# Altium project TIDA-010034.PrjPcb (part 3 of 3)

## Sheet TIDA-010034 MSP430.SchDoc: MSP430 for accessing registers of DP83825
size 431 x 279 mm; Date: Not shown in title block; ApprovedBy: Not shown in title block; CheckedBy: Not shown in title block; Author: Not shown in title block; CompanyName: Not shown in title block; DrawnBy: Surya Mishra; Engineer: Surya Mishra; Organization: Not shown in title block; Address1: Not shown in title block; Address2: Not shown in title block; Address3: Not shown in title block; Address4: Not shown in title block; DocumentNumber: 1; Revision: E1; SheetNumber: 8; SheetTotal: 9; PageSetup: Record=PageOptions¦CenterHorizontal=True¦CenterVertical=True¦PrintScale=1.00¦XCorrection=1.00¦YCorrection=1.00¦PrintKind=0¦BorderSize=5000000¦LeftOffset=0¦BottomOffset=0¦Orientation=2¦PaperLength=1000¦PaperWidth=1000¦Scale=100¦PaperSource=15¦PrintQuality=600¦MediaType=1¦DitherType=10¦PaperKind=Letter¦PrintScaleMode=1
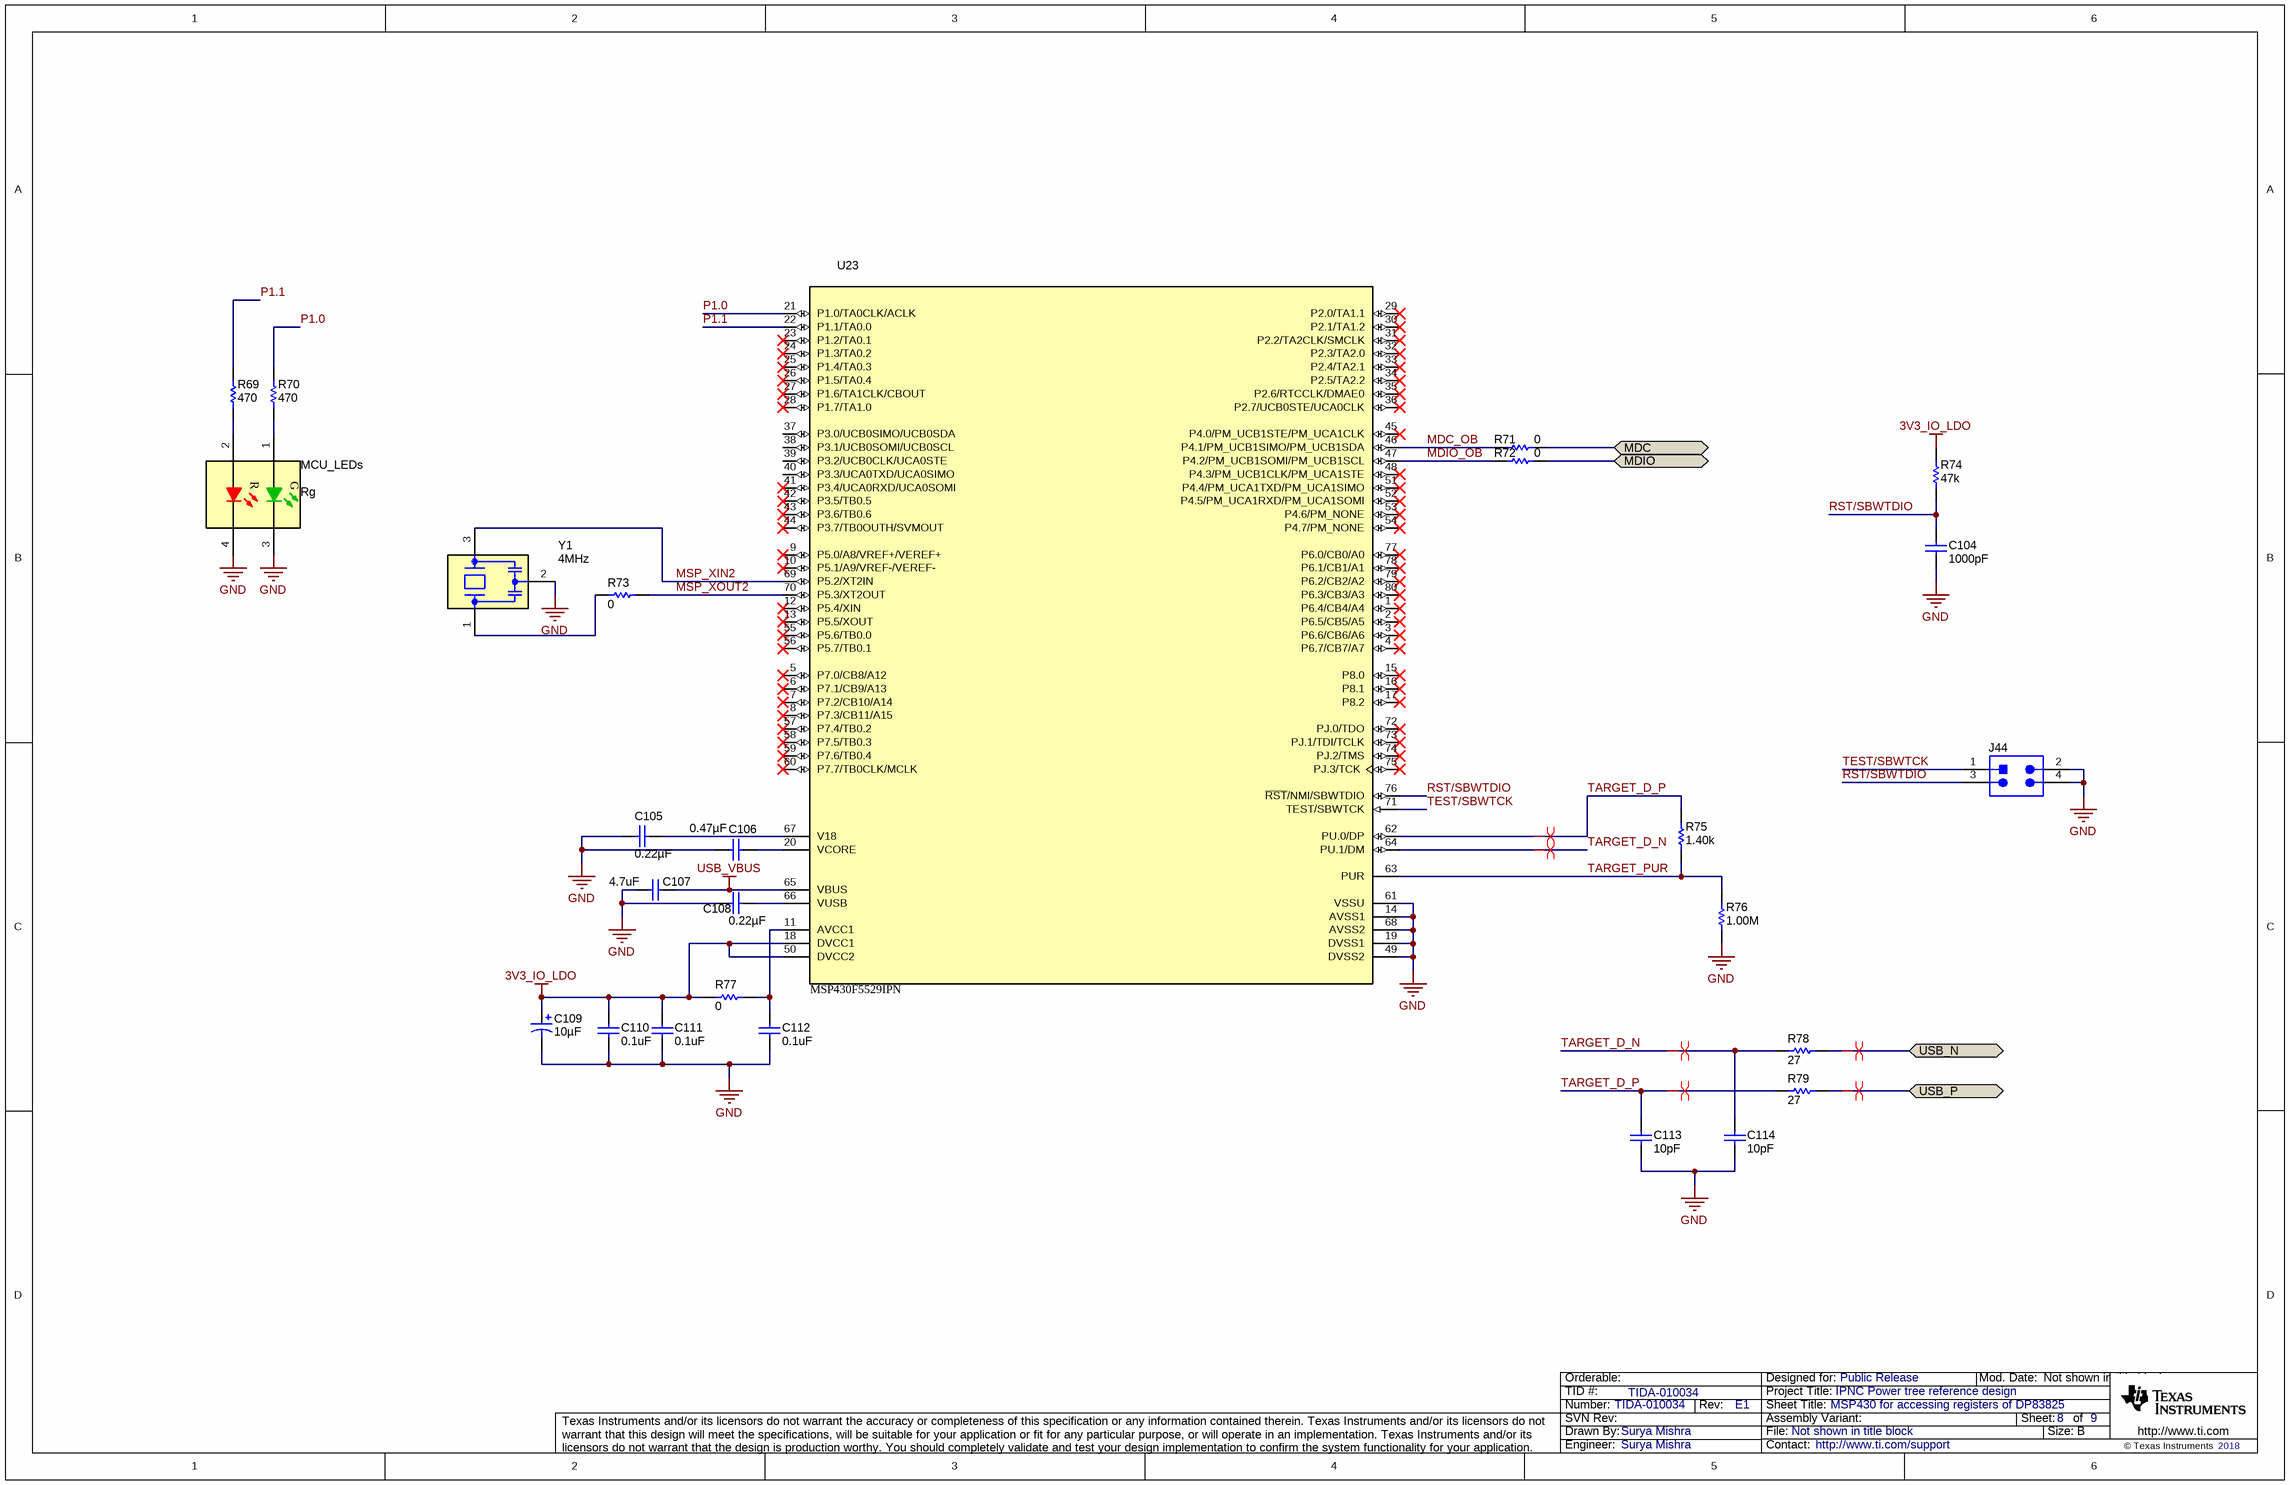
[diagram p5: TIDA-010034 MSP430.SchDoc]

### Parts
C104  ValueDisplayed: 1000pF  [0402]  (hidden comment: C1005NP01H102J050BA)
C105  ValueDisplayed: 0.22µF  [0603]  (hidden comment: GRM188R71H224KAC4D)
C106  ValueDisplayed: 0.47µF  [0603]  (hidden comment: GRM188R71E474KA12D)
C107  ValueDisplayed: 4.7uF  [0603]  (hidden comment: C1608X5R1V475K080AC)
C108  ValueDisplayed: 0.22µF  [0603]  (hidden comment: GRM188R71H224KAC4D)
C109  ValueDisplayed: 10µF  [CAPSMT_62_E61]  (hidden comment: EMZA350ADA100ME61G)
C110  ValueDisplayed: 0.1uF  [0402]  (hidden comment: GRM155R71C104KA88D)
C111  ValueDisplayed: 0.1uF  [0402]  (hidden comment: GRM155R71C104KA88D)
C112  ValueDisplayed: 0.1uF  [0402]  (hidden comment: GRM155R71C104KA88D)
C113  ValueDisplayed: 10pF  [0402]  (hidden comment: GRM1555C1H100RA01D)
C114  ValueDisplayed: 10pF  [0402]  (hidden comment: GRM1555C1H100RA01D)
J44  TSW-102-07-G-D  [TSW-102-07-G-D]  (value not drawn)
MCU_LEDs  value Rg  [HSMF-C165_RG]  (hidden comment: HSMF-C165)
R69  ValueDisplayed: 470  [0201]  (hidden comment: RC0201JR-07470RL)
R70  ValueDisplayed: 470  [0201]  (hidden comment: RC0201JR-07470RL)
R71  ValueDisplayed: 0  [0201M]  (hidden comment: ERJ-1GE0R00C)
R72  ValueDisplayed: 0  [0201M]  (hidden comment: ERJ-1GE0R00C)
R73  ValueDisplayed: 0  [0402]  (hidden comment: CRCW04020000Z0ED)
R74  ValueDisplayed: 47k  [0402]  (hidden comment: CRCW040247K0JNED)
R75  ValueDisplayed: 1.40k  [0402]  (hidden comment: CRCW04021K40FKED)
R76  ValueDisplayed: 1.00M  [0402]  (hidden comment: CRCW04021M00FKED)
R77  ValueDisplayed: 0  [0402]  (hidden comment: CRCW04020000Z0ED)
R78  ValueDisplayed: 27  [0402]  (hidden comment: CRCW040227R0JNED)
R79  ValueDisplayed: 27  [0402]  (hidden comment: CRCW040227R0JNED)
U23  MSP430F5529IPN  [PN0080A_N]
Y1  Frequency_Fixed: 4MHz  [Murata_CSTCR_G15L]  (hidden comment: CSTCR4M00G15L99-R0)

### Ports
MDC (bidir), MDIO (bidir), USB_N (bidir), USB_P (bidir)

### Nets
3V3_IO_LDO: C109.1(+) C110.2 C111.2 R74.1 R77.1 U23.18(DVCC1) U23.50(DVCC2)
GND: C104.1 C105.2 C106.2 C107.1 C108.2 C109.2(-) C110.1 C111.1 C112.1 C113.2 C114.2 J44.2 J44.4 MCU_LEDs.3(K) MCU_LEDs.4(K) R76.2 U23.14(AVSS1) U23.19(DVSS1) U23.49(DVSS2) U23.61(VSSU) U23.68(AVSS2) Y1.2(GND)
USB_VBUS: C107.2 U23.65(VBUS)
MDC: R71.1 ; port MDC
MDC_OB: R71.2 U23.46(P4.1/PM_UCB1SIMO/PM_UCB1SDA)
MDIO: R72.1 ; port MDIO
MDIO_OB: R72.2 U23.47(P4.2/PM_UCB1SOMI/PM_UCB1SCL)
MSP_XIN2: U23.69(P5.2/XT2IN) Y1.3(Out)
MSP_XOUT2: R73.2 U23.70(P5.3/XT2OUT)
P1.0: R70.2 U23.21(P1.0/TA0CLK/ACLK)
P1.1: R69.2 U23.22(P1.1/TA0.0)
RST/SBWTDIO: C104.2 J44.3 R74.2 U23.76(~{RST}/NMI/SBWTDIO)
TARGET_D_N: C114.1 R78.1 U23.64(PU.1/DM)
TARGET_D_P: C113.1 R75.2 R79.1 U23.62(PU.0/DP)
TARGET_PUR: R75.1 R76.1 U23.63(PUR)
TEST/SBWTCK: J44.1 U23.71(TEST/SBWTCK)
USB_N: R78.2 ; port USB_N
USB_P: R79.2 ; port USB_P
NetC105_1: C105.1 U23.67(V18)
NetC106_1: C106.1 U23.20(VCORE)
NetC108_1: C108.1 U23.66(VUSB)
NetC112_2: C112.2 R77.2 U23.11(AVCC1)
NetMCU_LEDs_1: MCU_LEDs.1(A) R70.1
NetMCU_LEDs_2: MCU_LEDs.2(A) R69.1
NetR73_1: R73.1 Y1.1(In)

Not connected (* = marked no-connect by the designer): U23 1(P6.4/CB4/A4)* 2(P6.5/CB5/A5)* 3(P6.6/CB6/A6)* 4(P6.7/CB7/A7)* 5(P7.0/CB8/A12)* 6(P7.1/CB9/A13)* 7(P7.2/CB10/A14)* 8(P7.3/CB11/A15)* 9(P5.0/A8/VREF+/VEREF+)* 10(P5.1/A9/VREF-/VEREF-)* 12(P5.4/XIN)* 13(P5.5/XOUT)* 15(P8.0)* 16(P8.1)* 17(P8.2)* 23(P1.2/TA0.1)* 24(P1.3/TA0.2)* 25(P1.4/TA0.3)* 26(P1.5/TA0.4)* 27(P1.6/TA1CLK/CBOUT)* 28(P1.7/TA1.0)* 29(P2.0/TA1.1)* 30(P2.1/TA1.2)* 31(P2.2/TA2CLK/SMCLK)* 32(P2.3/TA2.0)* 33(P2.4/TA2.1)* 34(P2.5/TA2.2)* 35(P2.6/RTCCLK/DMAE0)* 36(P2.7/UCB0STE/UCA0CLK)* 37(P3.0/UCB0SIMO/UCB0SDA) 38(P3.1/UCB0SOMI/UCB0SCL) 39(P3.2/UCB0CLK/UCA0STE) 40(P3.3/UCA0TXD/UCA0SIMO) 41(P3.4/UCA0RXD/UCA0SOMI)* 42(P3.5/TB0.5)* 43(P3.6/TB0.6)* 44(P3.7/TB0OUTH/SVMOUT)* 45(P4.0/PM_UCB1STE/PM_UCA1CLK)* 48(P4.3/PM_UCB1CLK/PM_UCA1STE)* 51(P4.4/PM_UCA1TXD/PM_UCA1SIMO)* 52(P4.5/PM_UCA1RXD/PM_UCA1SOMI)* 53(P4.6/PM_NONE)* 54(P4.7/PM_NONE)* 55(P5.6/TB0.0)* 56(P5.7/TB0.1)* 57(P7.4/TB0.2)* 58(P7.5/TB0.3)* 59(P7.6/TB0.4)* 60(P7.7/TB0CLK/MCLK)* 72(PJ.0/TDO)* 73(PJ.1/TDI/TCLK)* 74(PJ.2/TMS)* 75(PJ.3/TCK)* 77(P6.0/CB0/A0)* 78(P6.1/CB1/A1)* 79(P6.2/CB2/A2)* 80(P6.3/CB3/A3)*

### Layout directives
differential pair: TARGET_D_N, TARGET_D_P, USB_N, USB_P

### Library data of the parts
C104 = CMP-0006254-2: CAP, CERM, 1000 pF, 50 V, +/- 5%, C0G/NP0, 0402; Manufacturer: TDK; Polarized: N; Value: 1000pF; U/M: EA; Cap_F: 1nF; Value1: Unknown; VDC_V: 50V; TaMin_C: -55°C; TaMax_C: 150°C; SizeArea_mm2: 0.5; SizeAreaWB_mm2: 3; SizeX_mm: 1; SizeZ_mm: 0.6; AEC Category: Q200
C105 C108 = GRM188R71H224KAC4D: CAP, CERM, 0.22 µF, 50 V,+/- 10%, X7R, 0603; Manufacturer: MuRata; Polarized: N; CompType: Capacitor; Value: 0.22uF; U/M: EA; Cap_F: 0.00000022; Tolerance_%: 10; VDC_V: 50; Value2: 50V; TaMin_C: -55; TaMax_C: 125; SizeArea_mm2: 1.28; SizeAreaWB_mm2: 4.68; SizeX_mm: 1.6; SizeY_mm: 0.8; SizeZ_mm: 1; AEC Category: Q200
C106 = GRM188R71E474KA12D: CAP, CERM, 0.47 µF, 25 V,+/- 10%, X7R, 0603; Manufacturer: MuRata; Polarized: N; CompType: Capacitor; Value: 0.47uF; U/M: EA; Cap_F: 0.00000047; Tolerance_%: 10; VDC_V: 25; Value2: 25V; TaMin_C: -55; TaMax_C: 125; SizeArea_mm2: 1.28; SizeAreaWB_mm2: 4.68; SizeX_mm: 1.6; SizeY_mm: 0.8; SizeZ_mm: 1; AEC Category: Q200; Green_Lifecycle: Active; Green_REACh: Passed
C107 = CMP-0007022-5: CAP, CERM, 4.7 uF, 35 V, +/- 10%, X5R, 0603; Manufacturer: TDK; Polarized: N; CompType: Capacitor; Value: 4.7uF; U/M: EA; Cap_F: 4.7µF; ESR_ohm: 3.728m; Value1: 0.003728 ohm; VDC_V: 35V; IRMS_A: 2.69359A; TaMin_C: -55°C; TaMax_C: 85°C; SizeArea_mm2: 1.28; SizeAreaWB_mm2: 4.68; SizeX_mm: 1.6; SizeY_mm: 0.8; SizeZ_mm: 1; AEC Category: Q200
C109 = EMZA350ADA100ME61G: CAP, AL, 10 µF, 35 V, +/- 20%, 0.7 ohm, SMD; Manufacturer: Chemi-Con; Polarized: Y; CompType: Capacitor; Value: 10uF; U/M: EA; Cap_F: 0.00001; Tolerance_%: 20; Value1: 0.7 ohm; VDC_V: 35; Value2: 35V; ESR_ohm: 0.7; IRMS_A: 0.16; TaMin_C: -55; TaMax_C: 105; Cap_Case: E61; SizeAreaWB_mm2: 53.29; SizeArea_mm2: 28.09; SizeX_mm: 5.3; SizeZ_mm: 5.8; AEC Category: Q200
C110-C112 = CMP-0006641-2: CAP, CERM, 0.1 uF, 16 V, +/- 10%, X7R, 0402; Manufacturer: MuRata; Polarized: N; Value: 0.1uF; U/M: EA; Cap_F: 100nF; Value1: Unknown; VDC_V: 16V; TaMin_C: -55°C; TaMax_C: 125°C; AEC Category: Q200; SizeArea_mm2: 0.5; SizeAreaWB_mm2: 3; SizeX_mm: 1; SizeZ_mm: 0.6
C113 C114 = GRM1555C1H100RA01D: CAP, CERM, 10 pF, 50 V,+/- 4%, C0G/NP0, 0402; Manufacturer: MuRata; Polarized: N; CompType: Capacitor; Value: 10pF; U/M: EA; Cap_F: 0.00000000001; Tolerance_%: 4; VDC_V: 50; Value2: 50V; TaMin_C: -55; TaMax_C: 125; SizeArea_mm2: 0.5; SizeAreaWB_mm2: 3; SizeX_mm: 1; SizeZ_mm: 0.6; AEC Category: Q200
J44 = CMP-0075404-1: Header, 100mil, 2x2, Gold, TH; Manufacturer: Samtec; Pitch_mm: 2.54; Gender: Male; Shrouded: N; Row_Count: 2; Current_A: 6.3A; Voltage_V: 550V; Cert_CSA: Y; CNHeader: True; CT: False; Green_Lifecycle: Active; Green_REACh: Passed
MCU_LEDs = CMP-0002934-2: LED, Rg, SMD; Manufacturer: Avago; Vf_V: 2.2V; Io_A: 20mA; Vr_V: 5V; Ir_A: 100µA; Tjmax_C: 85°C; Value1: W; LuminousIntensity_IV: 20; Angle: 120; U/M: EA
R69 R70 = CMP-0027127-1: RES, 470, 5%, 0.05 W, 0201; Manufacturer: Yageo America; Power_W: 50mW; TempCo: 200 ppm/C; Value_Code: 470R; U/M: EA; Value: 470; EIA_Code: E24; SizeX_mm: 0.6; SizeY_mm: 0.3; SizeZ_mm: 0.26; Value2: 0.05W; SizeArea_mm2: 0.18; AEC Qualified: N; VDC_V: 25V; AEC Category: Q200
R71 R72 = CMP-0027011-4: RES, 0, 5%, 0.05 W, AEC-Q200 Grade 1, 0201; Manufacturer: Panasonic; Value: 0; Value_Code: 0000; Power_W: 50mW; Value2: 0.05W; VDC_V: 15V; TempCo: 600 ppm/C; EIA_Code: E24; AEC Category: Q200; AEC Grade: 1; AEC Qualified: Y; SizeArea_mm2: 0.18; SizeX_mm: 0.6; SizeY_mm: 0.3; SizeZ_mm: 0.26; SizeAreaWB_mm2: 2.08
R73 R77 = CMP-0026822-3: RES, 0, 5%, 0.063 W, AEC-Q200 Grade 0, 0402; Manufacturer: Vishay-Dale; Value: 0; Value_Code: 0000; Power_W: 63mW; Value2: 0.063W; VDC_V: 50V; TempCo: 200 ppm/C; EIA_Code: E24; AEC Category: Q200; AEC Qualified: Y; SizeArea_mm2: 0.5; SizeX_mm: 1; SizeZ_mm: 0.6
R74 = CMP-0026935-3: RES, 47 k, 5%, 0.063 W, AEC-Q200 Grade 0, 0402; Manufacturer: Vishay-Dale; Value: 47k; Value_Code: 47k0; Power_W: 63mW; Value2: 0.063W; VDC_V: 50V; TempCo: 200 ppm/C; EIA_Code: E24; AEC Category: Q200; AEC Qualified: Y; AEC Grade: 0; SizeArea_mm2: 0.5; SizeX_mm: 1; SizeZ_mm: 0.6
R75 = CMP-0026085-3: RES, 1.40 k, 1%, 0.063 W, AEC-Q200 Grade 0, 0402; Manufacturer: Vishay-Dale; Value: 1.40k; Res_ohm: 1.4k; Value_Code: 1k40; Power_W: 63mW; Value2: 0.063W; VDC_V: 50V; TempCo: 100 ppm/C; EIA_Code: E96; AEC Category: Q200; AEC Qualified: Y; AEC Grade: 0; SizeArea_mm2: 0.5; SizeX_mm: 1; SizeZ_mm: 0.6
R76 = CMP-0026100-2: RES, 1.00 M, 1%, 0.063 W, AEC-Q200 Grade 0, 0402; Manufacturer: Vishay-Dale; Value: 1.00Meg; Res_ohm: 1M; Value_Code: 1M00; Power_W: 63mW; Value2: 0.063W; VDC_V: 50V; TempCo: 100 ppm/C; EIA_Code: E96; AEC Category: Q200; AEC Qualified: Y; AEC Grade: 0; SizeArea_mm2: 0.5; SizeX_mm: 1; SizeZ_mm: 0.6
R78 R79 = CMP-0026888-3: RES, 27, 5%, 0.063 W, AEC-Q200 Grade 0, 0402; Manufacturer: Vishay-Dale; Value: 27; Value_Code: 27R0; Power_W: 63mW; Value2: 0.063W; VDC_V: 50V; TempCo: 200 ppm/C; EIA_Code: E24; AEC Category: Q200; AEC Qualified: Y; AEC Grade: 0; SizeArea_mm2: 0.5; SizeX_mm: 1; SizeZ_mm: 0.6
U23 = CMP-0038965-1: 25 MHz Mixed Signal Microcontroller with 128 KB Flash, 8192 B SRAM and 63 GPIOs, -40 to 85 degC, 80-pin QFP (PN), Green (RoHS & no Sb/Br); Manufacturer: Texas Instruments; ADC: 12-bit SAR; ADC Channels: 16; Brown Out Reset: Yes; DMA: 3; Flash(KB): 128; Frequency(MHz): 25; GPIO: 63; Multiplier: 32x32; SRAM(B): 8192; SubFamily: 5 Series; Timers - 16-bit: 4; USB: 1; USCI_A (UART/LIN/IrDA/SPI): 2
Y1 = CMP-0006148-5: Resonator, 4 MHz, 1000 ppm, 39 pF, SMD; Manufacturer: MuRata; SizeAreaWB_mm2: 16.5; SizeArea_mm2: 9; SizeX_mm: 4.5; SizeY_mm: 2; SizeZ_mm: 1.2; TaMin_C: 0°C; TaMax_C: 70°C; Frequency Stability: 800 ppm; AEC Category: Q200; AEC Qualified: N; Load Capacitance: 39 pF

## Sheet TIDA-010034 DP83825 ETHERNET PHY.SchDoc: DP83825 based Ethernet PHY
size 431 x 279 mm; Date: Not shown in title block; ApprovedBy: Not shown in title block; CheckedBy: Not shown in title block; Author: Not shown in title block; CompanyName: Not shown in title block; DrawnBy: Surya Mishra; Engineer: Surya Mishra; Organization: Not shown in title block; Address1: Not shown in title block; Address2: Not shown in title block; Address3: Not shown in title block; Address4: Not shown in title block; DocumentNumber: 1; Revision: E1; SheetNumber: 7; SheetTotal: 9; PageSetup: Record=PageOptions¦CenterHorizontal=True¦CenterVertical=True¦PrintScale=1.00¦XCorrection=1.00¦YCorrection=1.00¦PrintKind=0¦BorderSize=5000000¦LeftOffset=0¦BottomOffset=0¦Orientation=2¦PaperLength=1000¦PaperWidth=1000¦Scale=100¦PaperSource=15¦PrintQuality=600¦MediaType=1¦DitherType=10¦PaperKind=Letter¦PrintScaleMode=1
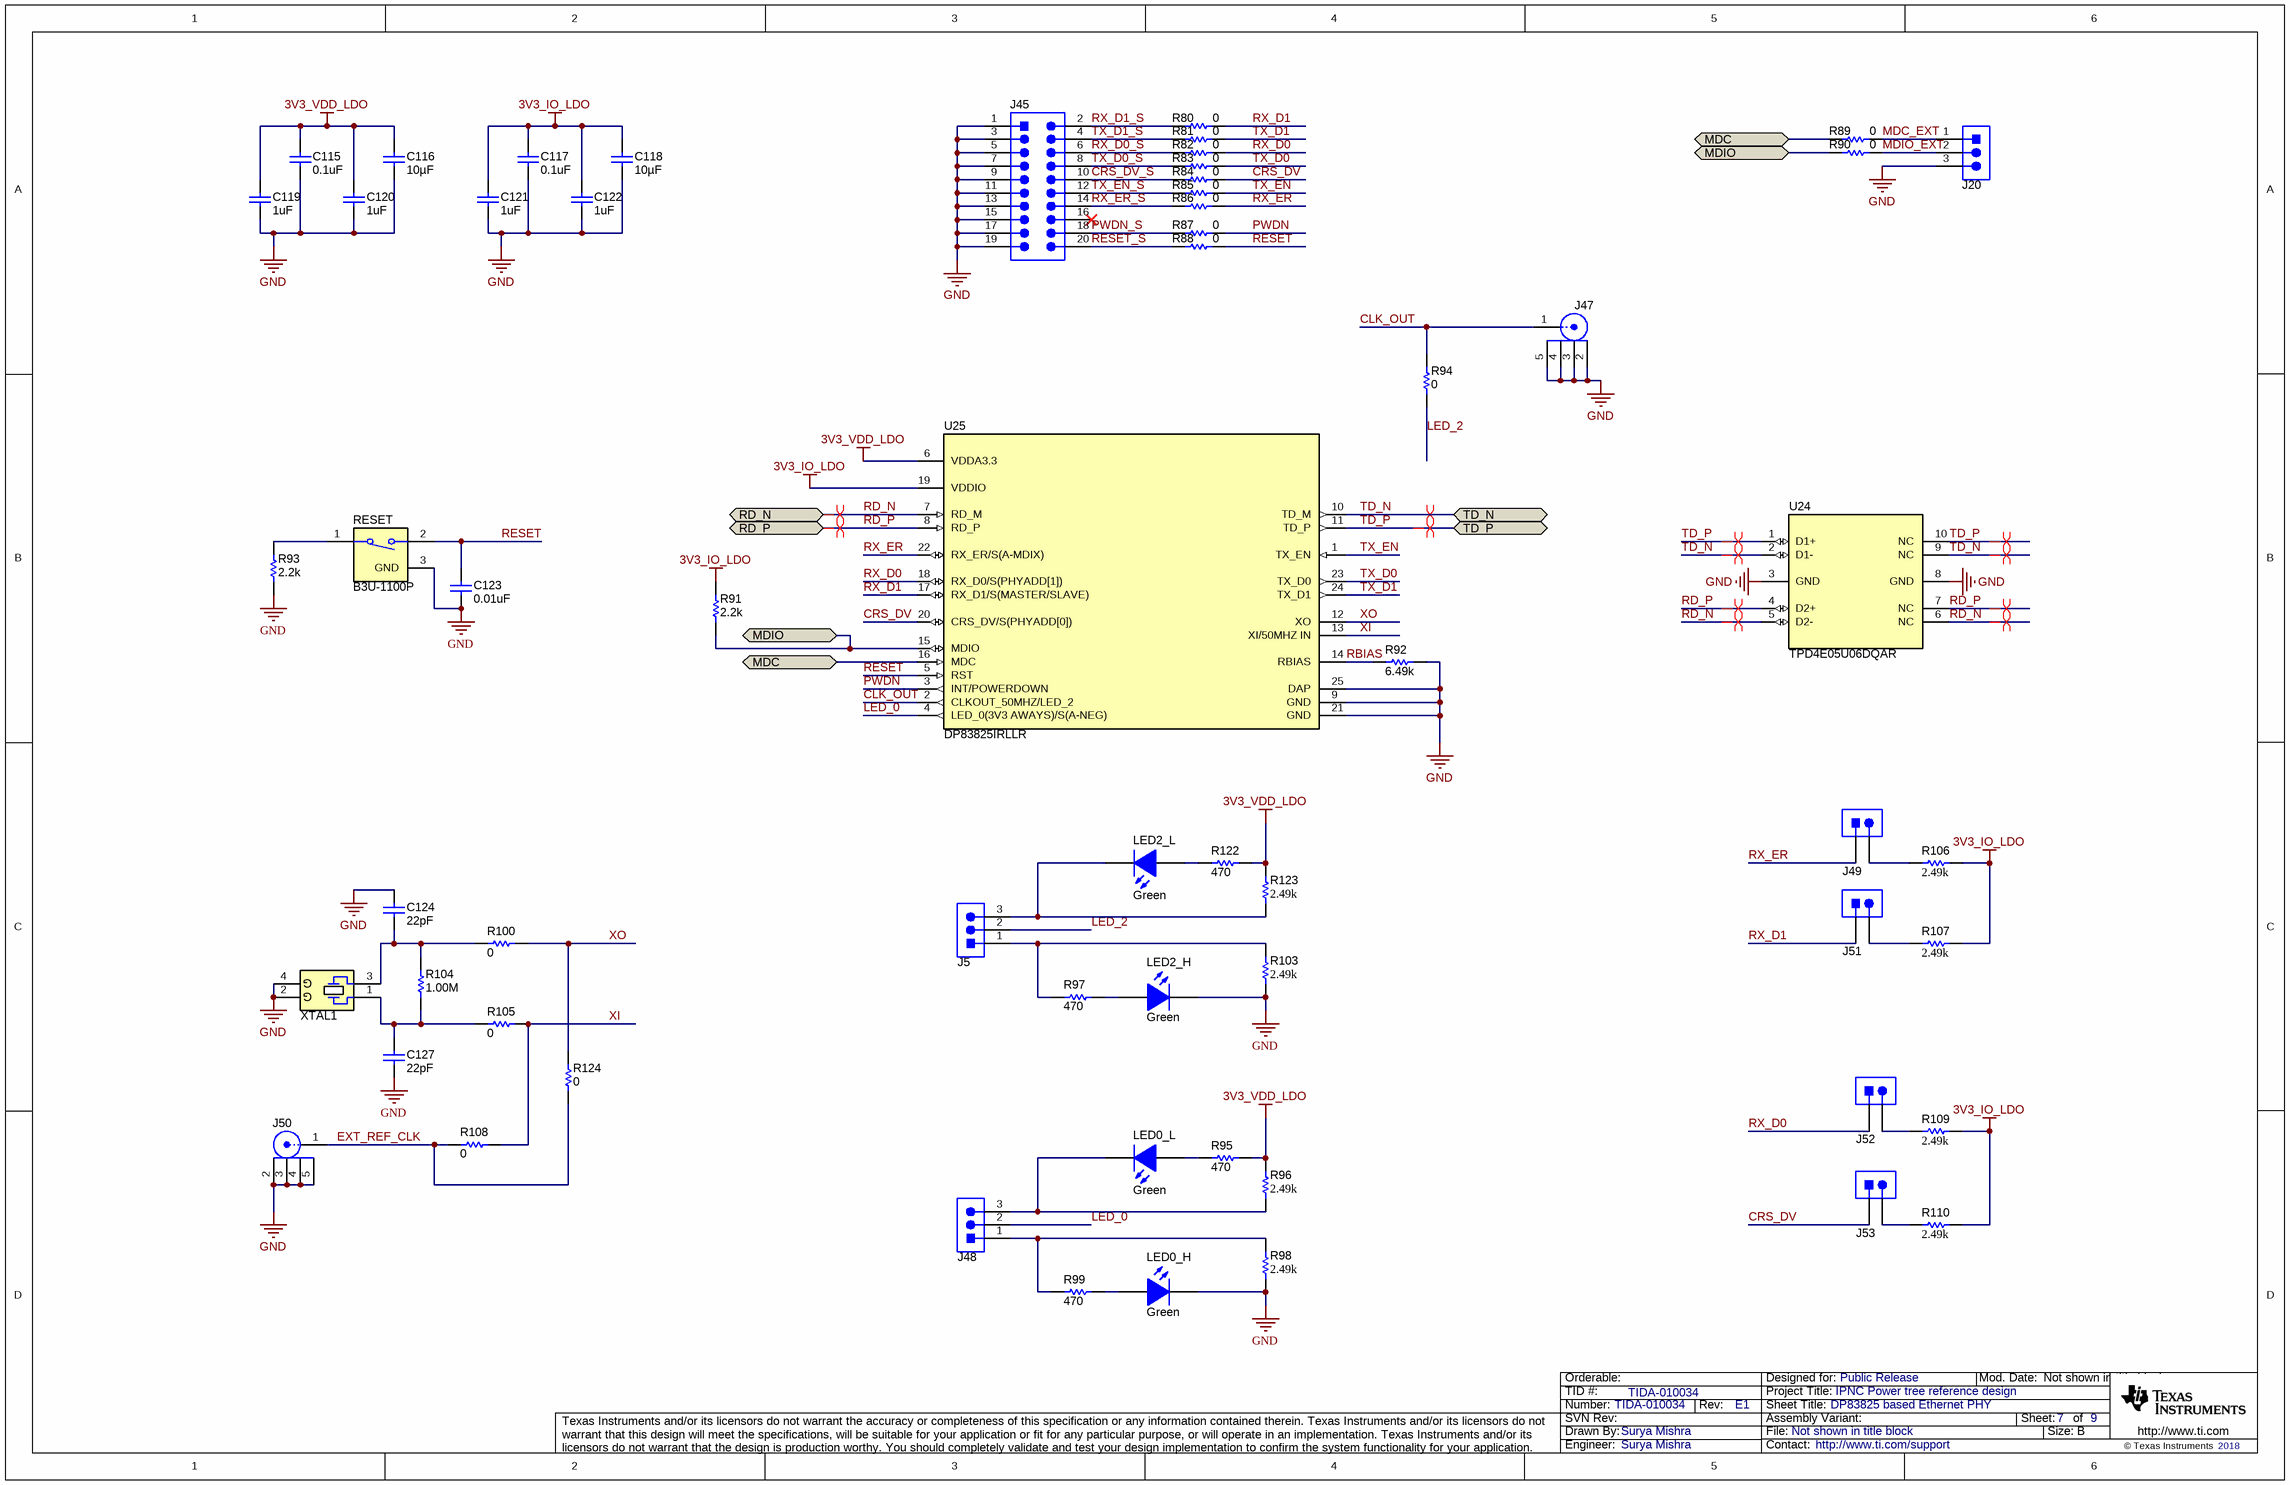
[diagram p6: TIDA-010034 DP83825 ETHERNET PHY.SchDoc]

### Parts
C115  ValueDisplayed: 0.1uF  [0402]  (hidden comment: GRM155R71C104KA88D)
C116  ValueDisplayed: 10µF  [0402]  (hidden comment: CL05A106MP8NUB8)
C117  ValueDisplayed: 0.1uF  [0402]  (hidden comment: GRM155R71C104KA88D)
C118  ValueDisplayed: 10µF  [0402]  (hidden comment: CL05A106MP8NUB8)
C119  ValueDisplayed: 1uF  [0402]  (hidden comment: GRM155R61A105KE15D)
C120  ValueDisplayed: 1uF  [0402]  (hidden comment: GRM155R61A105KE15D)
C121  ValueDisplayed: 1uF  [0402]  (hidden comment: GRM155R61A105KE15D)
C122  ValueDisplayed: 1uF  [0402]  (hidden comment: GRM155R61A105KE15D)
C123  ValueDisplayed: 0.01uF  [0402L]  (hidden comment: GRM155R71H103KA88D)
C124  ValueDisplayed: 22pF  [0402]  (hidden comment: GRM1555C1H220JA01D)
C127  ValueDisplayed: 22pF  [0402]  (hidden comment: GRM1555C1H220JA01D)
J5  HTSW-103-07-G-S  [Samtec_HTSW-103-07-G-S]  (value not drawn)
J20  HTSW-103-07-G-S  [Samtec_HTSW-103-07-G-S]  (value not drawn)
J45  PRPC010DAAN-RC  [Sullins_xxxC010DAAN]  (value not drawn)
J47  5-1814832-1  [TE_5-1814832-1]  (value not drawn)
J48  HTSW-103-07-G-S  [Samtec_HTSW-103-07-G-S]  (value not drawn)
J49  HTSW-102-07-G-S  [Samtec_HTSW-102-07-G-S]  (value not drawn)
J50  5-1814832-1  [TE_5-1814832-1]  (value not drawn)
J51  HTSW-102-07-G-S  [Samtec_HTSW-102-07-G-S]  (value not drawn)
J52  HTSW-102-07-G-S  [Samtec_HTSW-102-07-G-S]  (value not drawn)
J53  HTSW-102-07-G-S  [Samtec_HTSW-102-07-G-S]  (value not drawn)
LED0_H  value Green  [QTLP630C_Green]  (hidden comment: QTLP630C4TR)
LED0_L  value Green  [QTLP630C_Green]  (hidden comment: QTLP630C4TR)
LED2_H  value Green  [QTLP630C_Green]  (hidden comment: QTLP630C4TR)
LED2_L  value Green  [QTLP630C_Green]  (hidden comment: QTLP630C4TR)
R80  ValueDisplayed: 0  [0402]  (hidden comment: CRCW04020000Z0ED)
R81  ValueDisplayed: 0  [0402]  (hidden comment: CRCW04020000Z0ED)
R82  ValueDisplayed: 0  [0402]  (hidden comment: CRCW04020000Z0ED)
R83  ValueDisplayed: 0  [0402]  (hidden comment: CRCW04020000Z0ED)
R84  ValueDisplayed: 0  [0402]  (hidden comment: CRCW04020000Z0ED)
R85  ValueDisplayed: 0  [0402]  (hidden comment: CRCW04020000Z0ED)
R86  ValueDisplayed: 0  [0402]  (hidden comment: CRCW04020000Z0ED)
R87  ValueDisplayed: 0  [0402]  (hidden comment: CRCW04020000Z0ED)
R88  ValueDisplayed: 0  [0402]  (hidden comment: CRCW04020000Z0ED)
R89  ValueDisplayed: 0  [0402]  (hidden comment: CRCW04020000Z0ED)
R90  ValueDisplayed: 0  [0402]  (hidden comment: CRCW04020000Z0ED)
R91  ValueDisplayed: 2.2k  [0402]  (hidden comment: CRCW04022K20JNED)
R92  ValueDisplayed: 6.49k  [0402]  (hidden comment: CRCW04026K49FKED)
R93  ValueDisplayed: 2.2k  [0201M]  (hidden comment: CRCW02012K20JNED)
R94  ValueDisplayed: 0  [0402]  (hidden comment: CRCW04020000Z0ED)
R95  ValueDisplayed: 470  [0402]  (hidden comment: CRCW0402470RJNED)
R96  ValueDisplayed: 2.49k  [0402]  (hidden comment: CRCW04022K49FKED)
R97  ValueDisplayed: 470  [0402]  (hidden comment: CRCW0402470RJNED)
R98  ValueDisplayed: 2.49k  [0402]  (hidden comment: CRCW04022K49FKED)
R99  ValueDisplayed: 470  [0402]  (hidden comment: CRCW0402470RJNED)
R100  ValueDisplayed: 0  [0201M]  (hidden comment: ERJ-1GE0R00C)
R103  ValueDisplayed: 2.49k  [0402]  (hidden comment: CRCW04022K49FKED)
R104  ValueDisplayed: 1.00M  [0402]  (hidden comment: RC0402FR-071ML)
R105  ValueDisplayed: 0  [0201M]  (hidden comment: ERJ-1GE0R00C)
R106  ValueDisplayed: 2.49k  [0402]  (hidden comment: CRCW04022K49FKED)
R107  ValueDisplayed: 2.49k  [0402]  (hidden comment: CRCW04022K49FKED)
R108  ValueDisplayed: 0  [0201]  (hidden comment: ERJ-1GE0R00C)
R109  ValueDisplayed: 2.49k  [0402]  (hidden comment: CRCW04022K49FKED)
R110  ValueDisplayed: 2.49k  [0402]  (hidden comment: CRCW04022K49FKED)
R122  ValueDisplayed: 470  [0402]  (hidden comment: CRCW0402470RJNED)
R123  ValueDisplayed: 2.49k  [0402]  (hidden comment: CRCW04022K49FKED)
R124  ValueDisplayed: 0  [0201]  (hidden comment: ERJ-1GE0R00C)
RESET  B3U-1100P  [SW_B3U-1100P]
U24  TPD4E05U06DQAR  [DQA0010A]
U25  DP83825IRLLR  [RLL0024A]
XTAL1  ECS-250-12-33Q-JES-TR  [ECS_ECS-33Q]  (value not drawn)

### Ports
MDC (bidir), MDIO (bidir), RD_N (bidir), RD_P (bidir), TD_N (bidir), TD_P (bidir)

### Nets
3V3_IO_LDO: C117.2 C118.1 C121.1 C122.1 R91.1 R106.2 R107.2 R109.2 R110.2 U25.19(VDDIO)
3V3_VDD_LDO: C115.2 C116.1 C119.1 C120.1 R95.2 R96.2 R122.2 R123.2 U25.6(VDDA3.3)
GND: C115.1 C116.2 C117.1 C118.2 C119.2 C120.2 C121.2 C122.2 C123.1 C124.1 C127.2 J20.3 J45.1 J45.3 J45.5 J45.7 J45.9 J45.11 J45.13 J45.15 J45.17 J45.19 J47.2 J47.3 J47.4 J47.5 J50.2 J50.3 J50.4 J50.5 LED0_H.2(K) LED2_H.2(K) R92.2 R93.1 R98.1 R103.1 RESET.3(GND) U24.3(GND) U24.8(GND) U25.9(GND) U25.21(GND) U25.25(DAP) XTAL1.2(GND) XTAL1.4(GND)
CLK_OUT: J47.1 R94.2 U25.2(CLKOUT_50MHZ/LED_2)
CRS_DV: J53.1 R84.2 U25.20(CRS_DV/S(PHYADD[0]))
CRS_DV_S: J45.10 R84.1
EXT_REF_CLK: J50.1 R108.1 R124.1
LED_0: J48.2 U25.4(LED_0(3V3_AWAYS)/S(A-NEG))
LED_2: J5.2 R94.1
MDC: R89.1 U25.16(MDC) ; port MDC
MDC_EXT: J20.1 R89.2
MDIO: R90.1 R91.2 U25.15(MDIO) ; port MDIO
MDIO_EXT: J20.2 R90.2
PWDN: R87.2 U25.3(INT/POWERDOWN)
PWDN_S: J45.18 R87.1
RBIAS: R92.1 U25.14(RBIAS)
RD_N: U24.5(D2-) U24.6(NC) U25.7(RD_M) ; port RD_N
RD_P: U24.4(D2+) U24.7(NC) U25.8(RD_P) ; port RD_P
RESET: C123.2 R88.2 RESET.2 U25.5(RST)
RESET_S: J45.20 R88.1
RX_D0: J52.1 R82.2 U25.18(RX_D0/S(PHYADD[1]))
RX_D0_S: J45.6 R82.1
RX_D1: J51.1 R80.2 U25.17(RX_D1/S(MASTER/SLAVE))
RX_D1_S: J45.2 R80.1
RX_ER: J49.1 R86.2 U25.22(RX_ER/S(A-MDIX))
RX_ER_S: J45.14 R86.1
TD_N: U24.2(D1-) U24.9(NC) U25.10(TD_M) ; port TD_N
TD_P: U24.1(D1+) U24.10(NC) U25.11(TD_P) ; port TD_P
TX_D0: R83.2 U25.23(TX_D0)
TX_D0_S: J45.8 R83.1
TX_D1: R81.2 U25.24(TX_D1)
TX_D1_S: J45.4 R81.1
TX_EN: R85.2 U25.1(TX_EN)
TX_EN_S: J45.12 R85.1
XI: R105.2 R108.2 U25.13(XI/50MHZ_IN)
XO: R100.2 R124.2 U25.12(XO)
NetC124_2: C124.2 R100.1 R104.2 XTAL1.3
NetC127_1: C127.1 R104.1 R105.1 XTAL1.1
NetJ5_1: J5.1 R97.1 R103.2
NetJ5_3: J5.3 LED2_L.2(K) R123.1
NetJ48_1: J48.1 R98.2 R99.1
NetJ48_3: J48.3 LED0_L.2(K) R96.1
NetJ49_2: J49.2 R106.1
NetJ51_2: J51.2 R107.1
NetJ52_2: J52.2 R109.1
NetJ53_2: J53.2 R110.1
NetLED0_H_1: LED0_H.1(A) R99.2
NetLED0_L_1: LED0_L.1(A) R95.1
NetLED2_H_1: LED2_H.1(A) R97.2
NetLED2_L_1: LED2_L.1(A) R122.1
NetR93_2: R93.2 RESET.1

Not connected (* = marked no-connect by the designer): J45 16*

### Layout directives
differential pair: RD_N, RD_P, TD_N, TD_P

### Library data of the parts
C115 C117 = CMP-0006641-2: as C110 on sheet TIDA-010034 MSP430
C116 C118 = GRM155R61A106ME11: CAP, CERM, 10 µF, 10 V,+/- 20%, X5R, 0402; Manufacturer: Samsung Electro-Mechanics; Polarized: N; CompType: Capacitor; Value: 10uF; U/M: EA; Cap_F: 0.00001; Tolerance_%: 20; VDC_V: 10; Value2: 10V; TaMin_C: -55; TaMax_C: 85; SizeArea_mm2: 0.5; SizeAreaWB_mm2: 3; SizeX_mm: 1; SizeZ_mm: 0.6; AEC Category: Q200
C119 = CMP-0006563-2: CAP, CERM, 1 uF, 10 V, +/- 10%, X5R, 0402; Manufacturer: MuRata; Polarized: N; Value: 1uF; U/M: EA; Cap_F: 1µF; Value1: Unknown; VDC_V: 10V; TaMin_C: -55°C; TaMax_C: 85°C; AEC Category: Q200; SizeArea_mm2: 0.5; SizeAreaWB_mm2: 3; SizeX_mm: 1; SizeZ_mm: 0.6
C120-C122 = CMP-0006563-2: CAP, CERM, 1 uF, 10 V, +/- 10%, X5R, 0402; Manufacturer: MuRata; Polarized: N; CompType: Capacitor; Value: 1uF; U/M: EA; Cap_F: 1µF; Value1: Unknown; VDC_V: 10V; TaMin_C: -55°C; TaMax_C: 85°C; AEC Category: Q200; SizeArea_mm2: 0.5; SizeAreaWB_mm2: 3; SizeX_mm: 1; SizeZ_mm: 0.6
C123 = CMP-0006674-2: CAP, CERM, 0.01 uF, 50 V, +/- 10%, X7R, 0402; Manufacturer: MuRata; Polarized: N; CompType: Capacitor; Value: 0.01uF; U/M: EA; Cap_F: 10nF; Value1: Unknown; VDC_V: 50V; TaMin_C: -55°C; TaMax_C: 125°C; Cap_Case: 0402; AEC Category: Q200; SizeArea_mm2: 0.5; SizeAreaWB_mm2: 3; SizeX_mm: 1; SizeZ_mm: 0.6
C124 C127 = GRM1555C1H220JA01D: CAP, CERM, 22 pF, 50 V,+/- 5%, C0G/NP0, 0402; Manufacturer: MuRata; Polarized: N; CompType: Capacitor; Value: 22pF; U/M: EA; Cap_F: 0.000000000022; Tolerance_%: 5; VDC_V: 50; Value2: 50V; TaMin_C: -55; TaMax_C: 125; SizeArea_mm2: 0.5; SizeAreaWB_mm2: 3; SizeX_mm: 1; SizeZ_mm: 0.6; AEC Category: Q200; Green_Lifecycle: Active; Green_REACh: Passed
J5 J20 J48 = CMP-0075484-1: Header, 100mil, 3x1, Gold, TH; Manufacturer: Samtec; Green_REACh: Passed; CT: False; Green_Lifecycle: Active; CNHeader: True
J45 = CMP-0054591-2: Header, 2.54mm, 10x2, Gold, TH; Manufacturer: Sullins Connector Solutions; Shrouded: N; Gender: Male; Row_Count: 2; RowSpacing_mm: 2.54
J47 J50 = CMP-0054990-1: SMA Straight PCB Socket Die Cast, 50 Ohm, TH; Manufacturer: TE Connectivity; CNHeader: FALSE; Green_Lifecycle: Active; Green_REACh: Passed; CT: TRUE
J49 J51-J53 = CMP-0075483-1: Header, 100mil, 2x1, Gold, TH; Manufacturer: Samtec; Green_REACh: Passed; CT: False; Green_Lifecycle: Active; CNHeader: True
LED0_H LED0_L LED2_H LED2_L = CMP-0002917-1: LED, Green, SMD; Manufacturer: Everlight; Vf_V: 2.1V; Io_A: 20mA; Vr_V: 5V; Tjmax_C: 85°C; Value1: W; Angle: 140; U/M: EA
R80-R89 = CMP-0026822-3: RES, 0, 5%, 0.063 W, AEC-Q200 Grade 0, 0402; Manufacturer: Vishay-Dale; Power_W: 63mW; TempCo: 200 ppm/C; Value_Code: 0000; Value: 0; EIA_Code: E24; SizeX_mm: 1; SizeY_mm: 0.5; SizeZ_mm: 0.6; Value2: 0.063W; CompType: Resistor; AEC Qualified: Y; VDC_V: 50V; AEC Category: Q200
R90 R94 = CMP-0026822-3: RES, 0, 5%, 0.063 W, AEC-Q200 Grade 0, 0402; Manufacturer: Vishay-Dale; Power_W: 63mW; TempCo: 200 ppm/C; Value_Code: 0000; Value: 0; EIA_Code: E24; SizeX_mm: 1; SizeY_mm: 0.5; SizeZ_mm: 0.6; Value2: 0.063W; AEC Qualified: Y; VDC_V: 50V; AEC Category: Q200
R91 = CMP-0026890-5: RES, 2.2 k, 5%, 0.063 W, AEC-Q200 Grade 0, 0402; Manufacturer: Vishay-Dale; Power_W: 63mW; TempCo: 200 ppm/C; Value_Code: 2k20; Value: 2.2k; EIA_Code: E24; SizeX_mm: 1; SizeY_mm: 0.5; SizeZ_mm: 0.6; Value2: 0.063W; AEC Qualified: Y; VDC_V: 50V; AEC Category: Q200; AEC Grade: 0
R92 = CMP-0026515-2: RES, 6.49 k, 1%, 0.063 W, AEC-Q200 Grade 0, 0402; Manufacturer: Vishay-Dale; Power_W: 63mW; TempCo: 100 ppm/C; Value_Code: 6k49; Value: 6.49k; EIA_Code: E96; SizeX_mm: 1; SizeY_mm: 0.5; SizeZ_mm: 0.6; Value2: 0.063W; CompType: Resistor; AEC Qualified: Y; VDC_V: 50V; AEC Category: Q200; AEC Grade: 0
R93 = CMP-0027010-2: RES, 2.2 k, 5%, 0.05 W, 0201; Manufacturer: Vishay-Dale; Value: 2.2k; Value_Code: 2k20; Power_W: 50mW; Value2: 0.05W; VDC_V: 30V; TempCo: 200 ppm/C; EIA_Code: E24; AEC Category: Q200; AEC Qualified: N; SizeArea_mm2: 0.18; SizeX_mm: 0.6; SizeY_mm: 0.3; SizeZ_mm: 0.26
R95 R97 R99 R122 = CMP-0026934-3: RES, 470, 5%, 0.063 W, AEC-Q200 Grade 0, 0402; Manufacturer: Vishay-Dale; Power_W: 63mW; TempCo: 200 ppm/C; Value_Code: 470R; Value: 470; EIA_Code: E24; SizeX_mm: 1; SizeY_mm: 0.5; SizeZ_mm: 0.6; Value2: 0.063W; AEC Qualified: Y; VDC_V: 50V; AEC Category: Q200; AEC Grade: 0
R96 R98 R103 R106 R107 R109 R110 R123 = CMP-0026237-2: RES, 2.49 k, 1%, 0.063 W, AEC-Q200 Grade 0, 0402; Manufacturer: Vishay-Dale; Power_W: 63mW; TempCo: 100 ppm/C; Value_Code: 2k49; Value: 2.49k; EIA_Code: E96; SizeX_mm: 1; SizeY_mm: 0.5; SizeZ_mm: 0.6; Value2: 0.063W; AEC Qualified: Y; VDC_V: 50V; AEC Grade: 0; AEC Category: Q200
R100 R105 R108 R124 = CMP-0027011-4: as R71 on sheet TIDA-010034 MSP430
R104 = CMP-0026727-1: RES, 1.00 M, 1%, 0.063 W, 0402; Manufacturer: Yageo America; Value: 1.00Meg; Res_ohm: 1M; Value_Code: 1M00; Power_W: 63mW; Value2: 0.063W; TempCo: 100 ppm/C; EIA_Code: E96; U/M: EA; AEC Category: Q200; SizeArea_mm2: 0.5; SizeX_mm: 1; SizeZ_mm: 0.6
RESET = CMP-0002193-2: Switch, SPST-NO, Off-Mom, 12 V, SMD; Manufacturer: Omron Electronic Components; CurrentRating_mA: 50A; PositionCount: 1; VDC_V: 12V
U24 = CMP-0073613-3: 4-Channel Ultra-Low-Capacitance IEC ESD Protection Diode, DQA0010A (USON-10); Alternate Manufacturer: Texas Instruments; Green_Lifecycle: Active; SizeAreaWB_mm2: 7.0; Green_REACh: Passed; SizeZ_mm: 0.55; SizeX_mm: 1.0; SizeY_mm: 2.5; CompType: IC; AEC Category: Q200; AEC Qualified: N
U25 = CMP-0081932-1: DP83825IRLLR, RLL0024A (VQFN-24); Manufacturer: Texas Instruments; Alternate PartNumber: DP83825IRLLT; SizeAreaWB_mm2: 16; SizeArea_mm2: 9; AEC Qualified: N; AEC Category: Q200; SizeZ_mm: 1; SizeY_mm: 3; CompType: IC
XTAL1 = CMP-0079863-1: Crystal, 25 MHz, 20 ppm, AEC-Q200 Grade 1, SMD; Manufacturer: ECS Inc.; TaMin_C: -55°C; Frequency Tolerance: 20 ppm; Frequency Stability: 50 ppm; SizeAreaWB_mm2: 14.7; Frequency_Fixed: 25MHz; TaMax_C: 125°C; SizeZ_mm: 0.8; SizeX_mm: 2.5; SizeY_mm: 3.2; SizeArea_mm2: 8; AEC Qualified: Y; AEC Grade: 1; AEC Category: Q200

## Sheet TIDA-010034 Hardware.SchDoc: Hardware
size 431 x 279 mm; Date: Not shown in title block; ApprovedBy: Not shown in title block; CheckedBy: Not shown in title block; Author: Not shown in title block; CompanyName: Not shown in title block; DrawnBy: Surya Mishra; Engineer: Surya Mishra; Organization: Not shown in title block; Address1: Not shown in title block; Address2: Not shown in title block; Address3: Not shown in title block; Address4: Not shown in title block; DocumentNumber: 1; Revision: E1; SheetNumber: 9; SheetTotal: 9; PageSetup: Record=PageOptions¦CenterHorizontal=True¦CenterVertical=True¦PrintScale=1.00¦XCorrection=1.00¦YCorrection=1.00¦PrintKind=0¦BorderSize=5000000¦LeftOffset=0¦BottomOffset=0¦Orientation=2¦PaperLength=1000¦PaperWidth=1000¦Scale=100¦PaperSource=15¦PrintQuality=600¦MediaType=1¦DitherType=10¦PaperKind=Letter¦PrintScaleMode=1
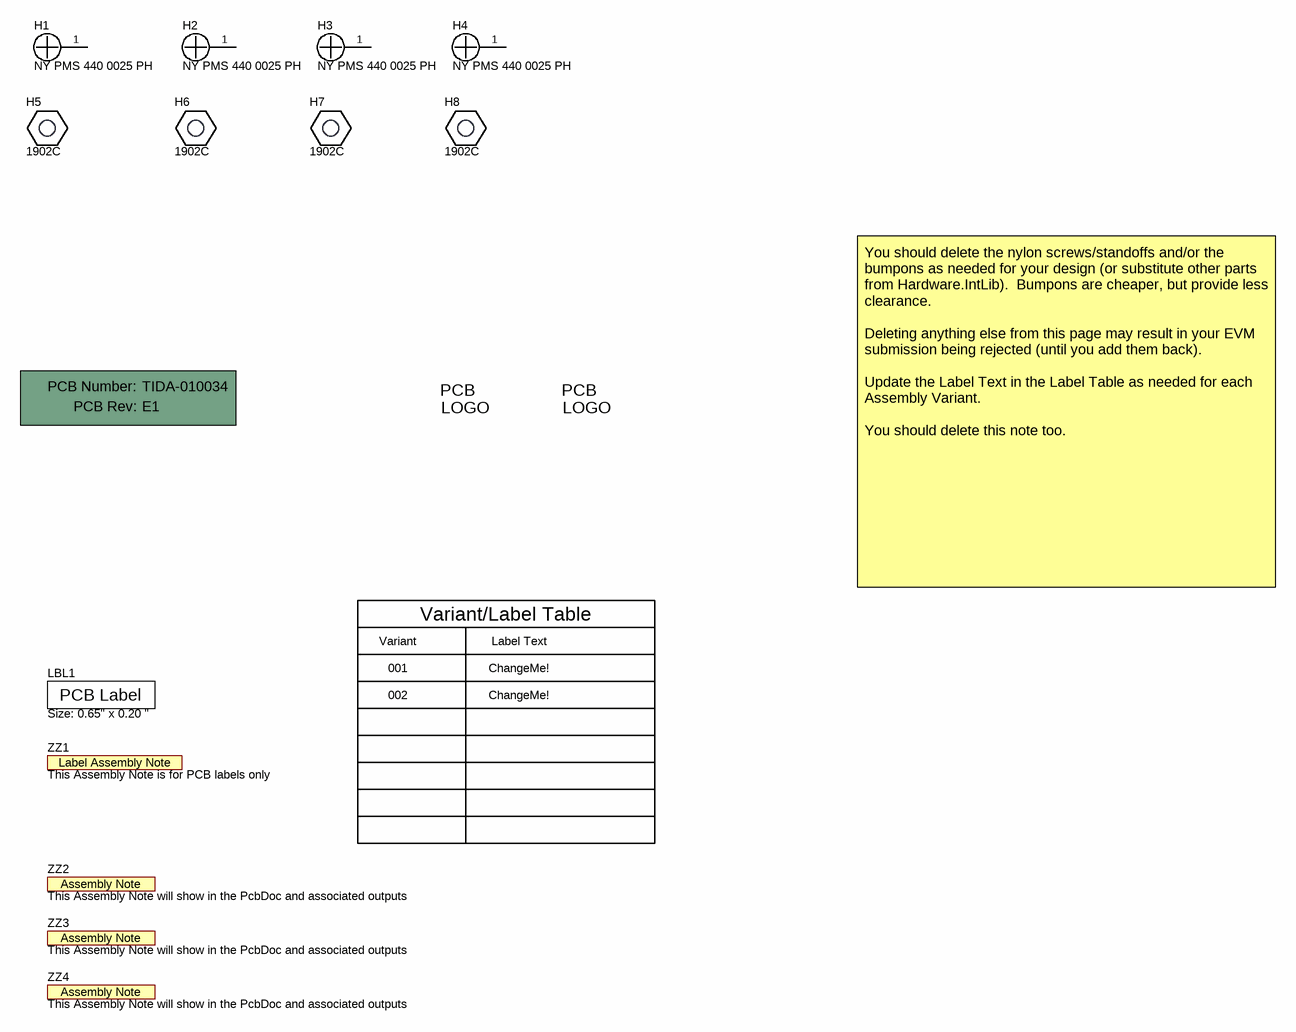
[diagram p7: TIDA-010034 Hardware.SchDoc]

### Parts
!PCB1  Printed Circuit Board  (value not drawn)  (mechanical)
H1  NY PMS 440 0025 PH  [NY PMS 440 0025 PH]
H2  NY PMS 440 0025 PH  [NY PMS 440 0025 PH]
H3  NY PMS 440 0025 PH  [NY PMS 440 0025 PH]
H4  NY PMS 440 0025 PH  [NY PMS 440 0025 PH]
H5  1902C  [Keystone_1902C]
H6  1902C  [Keystone_1902C]
H7  1902C  [Keystone_1902C]
H8  1902C  [Keystone_1902C]
LBL1  Size: 0.65" x 0.20 "  [Label_650x200]
Logo2  Pb-Free Symbol  [Pb-Free_Overlay_Small]  (value not drawn)  (no BOM)
Logo3  FCC disclaimer  [FCC_disclaimer]  (value not drawn)  (no BOM)
ZZ1  This Assembly Note is for PCB labels only  [AssemblyNoteLabel]  (no BOM)
ZZ2  This Assembly Note will show in the PcbDoc and associated outputs  [AssemblyNote]  (no BOM)
ZZ3  This Assembly Note will show in the PcbDoc and associated outputs  [AssemblyNote]  (no BOM)
ZZ4  This Assembly Note will show in the PcbDoc and associated outputs  [AssemblyNote]  (no BOM)

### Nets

Not connected (* = marked no-connect by the designer): H1 1; H2 1; H3 1; H4 1

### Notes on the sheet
- Variant
- Variant/Label Table
- Label Text
- You should delete the nylon screws/standoffs and/or the bumpons as needed for your design (or substitute other parts from Hardware.IntLib).  Bumpons are cheaper, but provide less clearance.
  Deleting anything else from this page may result in your EVM submission being rejected (until you add them back).
  Update the Label Text in the Label Table as needed for each Assembly Variant.
  You should delete this note too.
- 001
- 002
- ChangeMe!

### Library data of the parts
!PCB1 = PCB: Manufacturer: Any; PartNumber: TIDA-010034; SymbolCreator: a0412235
H1-H4 = NY PMS 440 0025 PH: Machine Screw, Round, #4-40 x 1/4, Nylon, Philips panhead; Manufacturer: B&F Fastener Supply; CompType: Hardware; SymbolCreator: codlsc; U/M: EA; Green_Lifecycle: Not Set; Green_REACh: Incomplete
H5-H8 = 1902C: Standoff, Hex, 0.5"L #4-40 Nylon; Manufacturer: Keystone; Green_Lifecycle: Active; Green_REACh: Passed; SymbolCreator: a0412235
LBL1 = THT-14-423-10: Thermal Transfer Printable Labels, 0.650" W x 0.200" H - 10,000 per roll; Manufacturer: Brady; SymbolCreator: a0412235; CompType: Label; Green_Lifecycle: Not Set; Green_REACh: Incomplete
Logo2 = Pb-Free: SymbolCreator: a0412235
Logo3 = FCC_disclaimer: SymbolCreator: a0412235
ZZ1 = AssemblyNoteLabel: SymbolCreator: a0412235
ZZ2-ZZ4 = AssemblyNote: SymbolCreator: codlsc

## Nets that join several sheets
3V3_IO_LDO: TIDA-010034 USB INPUT (C73.1 L17.2), TIDA-010034 MSP430 (7 pins), TIDA-010034 DP83825 ETHERNET PHY (10 pins)
3V3_VDD_LDO: TIDA-010034 USB INPUT (C63.1 L16.2), TIDA-010034 DP83825 ETHERNET PHY (9 pins)
GND: TIDA-010034 12V TO 5V TO POINT OF LOADS (71 pins), TIDA-010034 12V To POINT OF LOADS (69 pins), TIDA-010034 PoE INPUT (8 pins), TIDA-010034 USB INPUT (24 pins), TIDA-010034 TPS23755 PD FRONT-END (29 pins), TIDA-010034 MSP430 (22 pins), TIDA-010034 DP83825 ETHERNET PHY (44 pins)
USB_VBUS: TIDA-010034 USB INPUT (8 pins), TIDA-010034 MSP430 (C107.2 U23.65)
VPD: TIDA-010034 PoE INPUT (5 pins), TIDA-010034 TPS23755 PD FRONT-END (7 pins)
VSS: TIDA-010034 PoE INPUT (5 pins), TIDA-010034 TPS23755 PD FRONT-END (5 pins)
12V: TIDA-010034 12V TO 5V TO POINT OF LOADS (J23.1 J59.1), TIDA-010034 12V To POINT OF LOADS (6 pins), TIDA-010034 TPS23755 PD FRONT-END (7 pins)
MDC: TIDA-010034 MSP430 (R71.1), TIDA-010034 DP83825 ETHERNET PHY (R89.1 U25.16)
MDIO: TIDA-010034 MSP430 (R72.1), TIDA-010034 DP83825 ETHERNET PHY (R90.1 R91.2 U25.15)
RD_N: TIDA-010034 PoE INPUT (L13.4), TIDA-010034 DP83825 ETHERNET PHY (U24.5 U24.6 U25.7)
RD_P: TIDA-010034 PoE INPUT (L13.3), TIDA-010034 DP83825 ETHERNET PHY (U24.4 U24.7 U25.8)
TD_N: TIDA-010034 PoE INPUT (L11.4), TIDA-010034 DP83825 ETHERNET PHY (U24.2 U24.9 U25.10)
TD_P: TIDA-010034 PoE INPUT (L11.3), TIDA-010034 DP83825 ETHERNET PHY (U24.1 U24.10 U25.11)
USB_N: TIDA-010034 USB INPUT (J19.2 U11.2), TIDA-010034 MSP430 (R78.2)
USB_P: TIDA-010034 USB INPUT (J19.3 U11.1), TIDA-010034 MSP430 (R79.2)

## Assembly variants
001: not fitted +3.3V C9 C13 C62 C63 C64 C65 C66 C67 C68 C69 C70 C71 C72 C73 C104 C105 C106 C107 C108 C109 C110 C111 C112 C113 C114 C115 C116 C117 C118 C119 C120 C121 C122 C123 C124 C127 D5 D6 D12 D13 J5 J19 J20 J44 J45 J47 J48 J49 J50 J51 J52 J53 L3 L11 L13 L14 L16 L17 LED0_H LED0_L LED2_H LED2_L MCU_LEDs R23 R26 R49 R50 R51 R52 R53 R54 R69 R70 R71 R72 R73 R74 R75 R76 R77 R78 R79 R80 R81 R82 R83 R84 R85 R86 R87 R88 R89 R90 R91 R92 R93 R94 R95 R96 R97 R98 R99 R100 R103 R104 R105 R106 R107 R108 R109 R110 R112 R117 R122 R123 R124 R131 R132 RESET U10 U11 U12 U23 U24 U25 XTAL1 Y1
